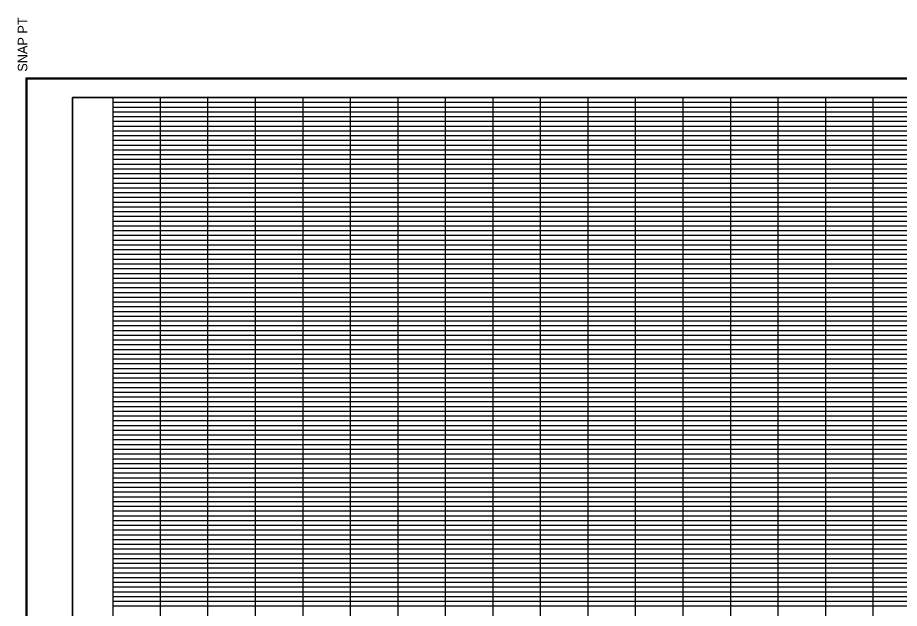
# Model space of a CAD drawing. Extents: x 980 to 1324, y 978 to 1767.
# Drawn here: x 979.9 to 1165.5, y 1642.5 to 1766.8 of the extents above; entities that cross this region are included whole.
import ezdxf

# ---------------------------------------------------------------- set-up
doc = ezdxf.new("R2010")
doc.units = 0
for name, color, linetype in [('DESIGN - SHEET - Corner Text', 7, 'Continuous'), ('DESIGN - SHEET - Light Grid', 7, 'Continuous'), ('DESIGN - SHEET - Linework', 7, 'Continuous'), ('DESIGN - SHEET - Plot Shape', 7, 'Continuous')]:
    doc.layers.add(name, color=color, linetype=linetype)

# ---------------------------------------------------------------- blocks, each defined once
blk = doc.blocks.new('XSTSHT')
at = {"layer": 'DESIGN - SHEET - Light Grid'}
for p, q in [((0, 20.9), (8, 20.9)), ((0, 20.8), (8, 20.8)), ((8, 20.9), (16, 20.9)), ((8, 20.8), (16, 20.8)), ((16, 20.9), (24, 20.9)), ((16, 20.8), (24, 20.8)), ((0, 20.7), (8, 20.7)), ((0, 20.6), (8, 20.6)), ((8, 20.7), (16, 20.7)), ((8, 20.6), (16, 20.6)), ((16, 20.7), (24, 20.7)), ((16, 20.6), (24, 20.6)), ((0, 20.5), (8, 20.5)), ((8, 20.5), (16, 20.5)), ((16, 20.5), (24, 20.5)), ((0, 20.4), (8, 20.4)), ((0, 20.3), (8, 20.3)), ((8, 20.4), (16, 20.4)), ((8, 20.3), (16, 20.3)), ((16, 20.4), (24, 20.4)), ((16, 20.3), (24, 20.3)), ((0, 20.2), (8, 20.2)), ((0, 20.1), (8, 20.1)), ((8, 20.2), (16, 20.2)), ((8, 20.1), (16, 20.1)), ((16, 20.2), (24, 20.2)), ((16, 20.1), (24, 20.1)), ((0, 19.9), (8, 19.9)), ((8, 19.9), (16, 19.9)), ((16, 19.9), (24, 19.9)), ((0, 19.8), (8, 19.8)), ((0, 19.7), (8, 19.7)), ((8, 19.8), (16, 19.8)), ((8, 19.7), (16, 19.7)), ((16, 19.8), (24, 19.8)), ((16, 19.7), (24, 19.7)), ((0, 19.6), (8, 19.6)), ((0, 19.5), (8, 19.5)), ((8, 19.6), (16, 19.6)), ((8, 19.5), (16, 19.5)), ((16, 19.6), (24, 19.6)), ((16, 19.5), (24, 19.5)), ((0, 19.4), (8, 19.4)), ((0, 19.3), (8, 19.3)), ((8, 19.4), (16, 19.4)), ((8, 19.3), (16, 19.3)), ((16, 19.4), (24, 19.4)), ((16, 19.3), (24, 19.3)), ((0, 19.2), (8, 19.2)), ((8, 19.2), (16, 19.2)), ((16, 19.2), (24, 19.2)), ((0, 19.1), (8, 19.1)), ((8, 19.1), (16, 19.1)), ((16, 19.1), (24, 19.1)), ((0, 18.9), (8, 18.9)), ((0, 18.8), (8, 18.8)), ((8, 18.9), (16, 18.9)), ((8, 18.8), (16, 18.8)), ((16, 18.9), (24, 18.9)), ((16, 18.8), (24, 18.8)), ((0, 18.7), (8, 18.7)), ((0, 18.6), (8, 18.6)), ((8, 18.7), (16, 18.7)), ((8, 18.6), (16, 18.6)), ((16, 18.7), (24, 18.7)), ((16, 18.6), (24, 18.6)), ((0, 18.5), (8, 18.5)), ((0, 18.4), (8, 18.4)), ((8, 18.5), (16, 18.5)), ((8, 18.4), (16, 18.4)), ((16, 18.5), (24, 18.5)), ((16, 18.4), (24, 18.4)), ((0, 18.3), (8, 18.3)), ((0, 18.2), (8, 18.2)), ((8, 18.3), (16, 18.3)), ((8, 18.2), (16, 18.2)), ((16, 18.3), (24, 18.3)), ((16, 18.2), (24, 18.2)), ((0, 18.1), (8, 18.1)), ((8, 18.1), (16, 18.1)), ((16, 18.1), (24, 18.1)), ((0, 17.9), (8, 17.9)), ((8, 17.9), (16, 17.9)), ((16, 17.9), (24, 17.9)), ((0, 17.8), (8, 17.8)), ((0, 17.7), (8, 17.7)), ((8, 17.8), (16, 17.8)), ((8, 17.7), (16, 17.7)), ((16, 17.8), (24, 17.8)), ((16, 17.7), (24, 17.7)), ((0, 17.6), (8, 17.6)), ((0, 17.5), (8, 17.5)), ((8, 17.6), (16, 17.6)), ((8, 17.5), (16, 17.5)), ((16, 17.6), (24, 17.6)), ((16, 17.5), (24, 17.5)), ((0, 17.4), (8, 17.4)), ((0, 17.3), (8, 17.3)), ((8, 17.4), (16, 17.4)), ((8, 17.3), (16, 17.3)), ((16, 17.4), (24, 17.4)), ((16, 17.3), (24, 17.3)), ((0, 17.2), (8, 17.2)), ((0, 17.1), (8, 17.1)), ((8, 17.2), (16, 17.2)), ((8, 17.1), (16, 17.1)), ((16, 17.2), (24, 17.2)), ((16, 17.1), (24, 17.1)), ((0, 16.9), (8, 16.9)), ((8, 16.9), (16, 16.9)), ((16, 16.9), (24, 16.9)), ((0, 16.8), (8, 16.8)), ((8, 16.8), (16, 16.8)), ((16, 16.8), (24, 16.8)), ((0, 16.7), (8, 16.7)), ((0, 16.6), (8, 16.6)), ((8, 16.7), (16, 16.7)), ((8, 16.6), (16, 16.6)), ((16, 16.7), (24, 16.7)), ((16, 16.6), (24, 16.6)), ((0, 16.5), (8, 16.5)), ((0, 16.4), (8, 16.4)), ((8, 16.5), (16, 16.5)), ((8, 16.4), (16, 16.4)), ((16, 16.5), (24, 16.5)), ((16, 16.4), (24, 16.4)), ((0, 16.3), (8, 16.3)), ((0, 16.2), (8, 16.2)), ((8, 16.3), (16, 16.3)), ((8, 16.2), (16, 16.2)), ((16, 16.3), (24, 16.3)), ((16, 16.2), (24, 16.2)), ((0, 16.1), (8, 16.1)), ((8, 16.1), (16, 16.1)), ((16, 16.1), (24, 16.1)), ((0, 15.9), (8, 15.9)), ((0, 15.8), (8, 15.8)), ((8, 15.9), (16, 15.9)), ((8, 15.8), (16, 15.8)), ((16, 15.9), (24, 15.9)), ((16, 15.8), (24, 15.8)), ((0, 15.7), (8, 15.7)), ((0, 15.6), (8, 15.6)), ((8, 15.7), (16, 15.7)), ((8, 15.6), (16, 15.6)), ((16, 15.7), (24, 15.7)), ((16, 15.6), (24, 15.6)), ((0, 15.5), (8, 15.5)), ((8, 15.5), (16, 15.5)), ((16, 15.5), (24, 15.5)), ((0, 15.4), (8, 15.4)), ((0, 15.3), (8, 15.3)), ((8, 15.4), (16, 15.4)), ((8, 15.3), (16, 15.3)), ((16, 15.4), (24, 15.4)), ((16, 15.3), (24, 15.3)), ((0, 15.2), (8, 15.2)), ((0, 15.1), (8, 15.1)), ((8, 15.2), (16, 15.2)), ((8, 15.1), (16, 15.1)), ((16, 15.2), (24, 15.2)), ((16, 15.1), (24, 15.1)), ((0, 14.9), (8, 14.9)), ((8, 14.9), (16, 14.9)), ((16, 14.9), (24, 14.9)), ((0, 14.8), (8, 14.8)), ((0, 14.7), (8, 14.7)), ((8, 14.8), (16, 14.8)), ((8, 14.7), (16, 14.7)), ((16, 14.8), (24, 14.8)), ((16, 14.7), (24, 14.7)), ((0, 14.6), (8, 14.6)), ((0, 14.5), (8, 14.5)), ((8, 14.6), (16, 14.6)), ((8, 14.5), (16, 14.5)), ((16, 14.6), (24, 14.6)), ((16, 14.5), (24, 14.5)), ((0, 14.4), (8, 14.4)), ((0, 14.3), (8, 14.3)), ((8, 14.4), (16, 14.4)), ((8, 14.3), (16, 14.3)), ((16, 14.4), (24, 14.4)), ((16, 14.3), (24, 14.3)), ((0, 14.2), (8, 14.2)), ((8, 14.2), (16, 14.2)), ((16, 14.2), (24, 14.2)), ((0, 14.1), (8, 14.1)), ((8, 14.1), (16, 14.1)), ((16, 14.1), (24, 14.1)), ((0, 13.9), (8, 13.9)), ((0, 13.8), (8, 13.8)), ((8, 13.9), (16, 13.9)), ((8, 13.8), (16, 13.8)), ((16, 13.9), (24, 13.9)), ((16, 13.8), (24, 13.8)), ((0, 13.7), (8, 13.7)), ((0, 13.6), (8, 13.6)), ((8, 13.7), (16, 13.7)), ((8, 13.6), (16, 13.6)), ((16, 13.7), (24, 13.7)), ((16, 13.6), (24, 13.6)), ((0, 13.5), (8, 13.5)), ((0, 13.4), (8, 13.4)), ((8, 13.5), (16, 13.5)), ((8, 13.4), (16, 13.4)), ((16, 13.5), (24, 13.5)), ((16, 13.4), (24, 13.4)), ((0, 13.3), (8, 13.3)), ((0, 13.2), (8, 13.2)), ((8, 13.3), (16, 13.3)), ((8, 13.2), (16, 13.2)), ((16, 13.3), (24, 13.3)), ((16, 13.2), (24, 13.2)), ((0, 13.1), (8, 13.1)), ((8, 13.1), (16, 13.1)), ((16, 13.1), (24, 13.1)), ((0, 12.9), (8, 12.9)), ((8, 12.9), (16, 12.9)), ((16, 12.9), (24, 12.9)), ((0, 12.8), (8, 12.8)), ((0, 12.7), (8, 12.7)), ((8, 12.8), (16, 12.8)), ((8, 12.7), (16, 12.7)), ((16, 12.8), (24, 12.8)), ((16, 12.7), (24, 12.7)), ((0, 12.6), (8, 12.6)), ((0, 12.5), (8, 12.5)), ((8, 12.6), (16, 12.6)), ((8, 12.5), (16, 12.5)), ((16, 12.6), (24, 12.6)), ((16, 12.5), (24, 12.5)), ((0, 12.4), (8, 12.4)), ((0, 12.3), (8, 12.3)), ((8, 12.4), (16, 12.4)), ((8, 12.3), (16, 12.3)), ((16, 12.4), (24, 12.4)), ((16, 12.3), (24, 12.3)), ((0, 12.2), (8, 12.2)), ((0, 12.1), (8, 12.1)), ((8, 12.2), (16, 12.2)), ((8, 12.1), (16, 12.1)), ((16, 12.2), (24, 12.2)), ((16, 12.1), (24, 12.1)), ((0, 11.9), (8, 11.9)), ((8, 11.9), (16, 11.9)), ((16, 11.9), (24, 11.9)), ((0, 11.8), (8, 11.8)), ((0, 11.7), (8, 11.7)), ((8, 11.8), (16, 11.8)), ((8, 11.7), (16, 11.7)), ((16, 11.8), (24, 11.8)), ((16, 11.7), (24, 11.7)), ((0, 11.6), (8, 11.6)), ((8, 11.6), (16, 11.6)), ((16, 11.6), (24, 11.6)), ((0, 11.5), (8, 11.5)), ((0, 11.4), (8, 11.4)), ((8, 11.5), (16, 11.5)), ((8, 11.4), (16, 11.4)), ((16, 11.5), (24, 11.5)), ((16, 11.4), (24, 11.4)), ((0, 11.3), (8, 11.3)), ((0, 11.2), (8, 11.2)), ((8, 11.3), (16, 11.3)), ((8, 11.2), (16, 11.2)), ((16, 11.3), (24, 11.3)), ((16, 11.2), (24, 11.2)), ((0, 11.1), (8, 11.1)), ((8, 11.1), (16, 11.1)), ((16, 11.1), (24, 11.1)), ((0, 10.9), (8, 10.9)), ((0, 10.8), (8, 10.8)), ((8, 10.9), (16, 10.9)), ((8, 10.8), (16, 10.8)), ((16, 10.9), (24, 10.9)), ((16, 10.8), (24, 10.8)), ((0, 10.7), (8, 10.7)), ((0, 10.6), (8, 10.6)), ((8, 10.7), (16, 10.7)), ((8, 10.6), (16, 10.6)), ((16, 10.7), (24, 10.7)), ((16, 10.6), (24, 10.6)), ((0, 10.5), (8, 10.5)), ((0, 10.4), (8, 10.4)), ((8, 10.5), (16, 10.5)), ((8, 10.4), (16, 10.4)), ((16, 10.5), (24, 10.5)), ((16, 10.4), (24, 10.4)), ((0, 10.3), (8, 10.3)), ((8, 10.3), (16, 10.3)), ((16, 10.3), (24, 10.3))]:
    blk.add_line(p, q, dxfattribs=at)
at = {"layer": 'DESIGN - SHEET - Linework'}
for p, q in [((-1.823, -0.414), (-1.823, 21.414)), ((-1.823, 21.414), (32.217, 21.414)), ((1, 0), (1, 21)), ((2, 0), (2, 21)), ((3, 0), (3, 21)), ((4, 0), (4, 21)), ((5, 0), (5, 21)), ((6, 0), (6, 21)), ((7, 0), (7, 21)), ((8, 0), (8, 21)), ((9, 0), (9, 21)), ((10, 0), (10, 21)), ((11, 0), (11, 21)), ((12, 0), (12, 21)), ((13, 0), (13, 21)), ((14, 0), (14, 21)), ((15, 0), (15, 21)), ((16, 0), (16, 21)), ((0, 20), (28, 20)), ((0, 19), (32, 19)), ((0, 18), (32, 18)), ((0, 17), (32, 17)), ((0, 16), (32, 16)), ((0, 15), (32, 15)), ((0, 14), (32, 14)), ((0, 13), (32, 13)), ((0, 12), (32, 12)), ((0, 11), (32, 11))]:
    blk.add_line(p, q, dxfattribs=at)
blk.add_lwpolyline([(0, 21), (0, 0), (32, 0), (32, 21), (0, 21)], dxfattribs=at)
at = {"layer": 'DESIGN - SHEET - Plot Shape'}
for points in [[(-1.803, 21.394), (32.197, 21.394), (32.197, -0.394), (-1.803, -0.394)], [(-0.85, 21), (32, 21), (32, -0.25), (-0.85, -0.25)]]:
    blk.add_lwpolyline(points, close=True, dxfattribs=at)
at = {"layer": 'DESIGN - SHEET - Corner Text'}
blk.add_text('  SNAP PT', height=0.2, rotation=90, dxfattribs=at).set_placement((-1.803, 21.394))

msp = doc.modelspace()

# ---------------------------------------------------------------- linework, layer by layer
at = {"layer": 'DESIGN - SHEET - Plot Shape'}
msp.add_lwpolyline([(991.5, 1537.5), (1320, 1537.5), (1320, 1750), (991.5, 1750)], close=True, dxfattribs=at)

# ---------------------------------------------------------------- block references
at = {"layer": 'DESIGN - SHEET - Plot Shape', "xscale": 10, "yscale": 10}
msp.add_blockref('XSTSHT', (1000, 1540), dxfattribs=at)

doc.saveas('drawing.dxf')
